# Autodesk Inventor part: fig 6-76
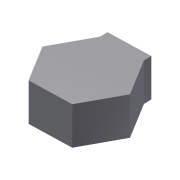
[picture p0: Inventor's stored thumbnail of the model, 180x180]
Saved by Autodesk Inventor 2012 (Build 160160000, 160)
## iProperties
Created: 2009-03
Part Number: fig 6-76
Document SubType Name: Modeling
Designer: Sham
Density: 1 g/cm^3
Material: Default
Author: Sham
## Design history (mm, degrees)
sketch "Sketch5"
  geometry: L1 (-5.929, 9.627)-(5.372, 9.948); L2 (5.372, 9.948)-(11.301, 0.321); L3 (11.301, 0.321)-(5.929, -9.627); L4 (5.929, -9.627)-(-5.372, -9.948); L5 (-5.372, -9.948)-(-11.301, -0.321); L6 (-11.301, -0.321)-(-5.929, 9.627); 1 further point
  constraints: 12 end point, 13 other
extrude "Extrusion3" new body sketch "Sketch5" distance "d13" = 10; taper "d14" = 0 deg
thicken "Thicken2" dims "d15" = 2, "d16" = 2
body "Solid4"
